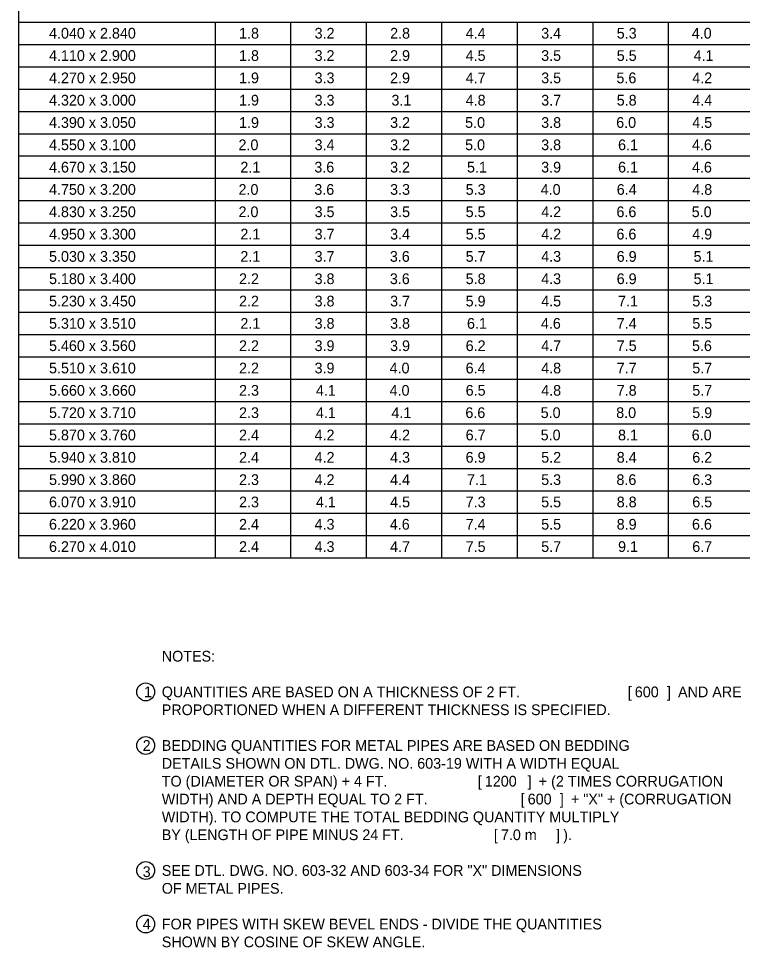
# Model space of a CAD drawing. Extents: x 49991.4 to 50047.6, y 49987.6 to 50011.4.
# Drawn here: x 50039.46 to 50043.52, y 49988.2 to 49993.4 of the extents above; entities that cross this region are included whole.
import ezdxf

# ---------------------------------------------------------------- set-up
doc = ezdxf.new("R2010")
doc.units = 0
doc.layers.add('Default', color=7, linetype='Continuous')
doc.layers.add('Level 2', color=7, linetype='Continuous')

msp = doc.modelspace()

# ---------------------------------------------------------------- linework, layer by layer
at = {"layer": 'Default'}
msp.add_circle((50040.1762, 49988.3294), 0.05, dxfattribs=at)
at = {"layer": 'Level 2'}
for p, q in [((50039.4641, 49998.1607), (50039.4641, 49990.3807)), ((50039.4641, 49993.3807), (50047.3341, 49993.3807)), ((50040.5645, 49993.3807), (50040.5645, 49990.3807)), ((50040.9876, 49993.3807), (50040.9876, 49990.3807)), ((50041.4107, 49993.3807), (50041.4107, 49990.3807)), ((50041.8338, 49993.3807), (50041.8338, 49990.3807)), ((50042.2569, 49993.3807), (50042.2569, 49990.3807)), ((50042.68, 49993.3807), (50042.68, 49990.3807)), ((50043.1031, 49993.3807), (50043.1031, 49990.3807)), ((50039.4641, 49993.2557), (50047.3341, 49993.2557)), ((50039.4641, 49993.1307), (50047.3341, 49993.1307)), ((50039.4641, 49993.0057), (50047.3341, 49993.0057)), ((50039.4641, 49992.8807), (50047.3341, 49992.8807)), ((50039.4641, 49992.7557), (50047.3341, 49992.7557)), ((50039.4641, 49992.6307), (50047.3341, 49992.6307)), ((50039.4641, 49992.5057), (50047.3341, 49992.5057)), ((50039.4641, 49992.3807), (50047.3341, 49992.3807)), ((50039.4641, 49992.2557), (50047.3341, 49992.2557)), ((50039.4641, 49992.1307), (50047.3341, 49992.1307)), ((50039.4641, 49992.0057), (50047.3341, 49992.0057)), ((50039.4641, 49991.8807), (50047.3341, 49991.8807)), ((50039.4641, 49991.7557), (50047.3341, 49991.7557)), ((50039.4641, 49991.6307), (50047.3341, 49991.6307)), ((50039.4641, 49991.5057), (50047.3341, 49991.5057)), ((50039.4641, 49991.3807), (50047.3341, 49991.3807)), ((50039.4641, 49991.2557), (50047.3341, 49991.2557)), ((50039.4641, 49991.1307), (50047.3341, 49991.1307)), ((50039.4641, 49991.0057), (50047.3341, 49991.0057)), ((50039.4641, 49990.8807), (50047.3341, 49990.8807)), ((50039.4641, 49990.7557), (50047.3341, 49990.7557)), ((50039.4641, 49990.6307), (50047.3341, 49990.6307)), ((50039.4641, 49990.5057), (50047.3341, 49990.5057)), ((50039.4641, 49990.3807), (50047.3341, 49990.3807))]:
    msp.add_line(p, q, dxfattribs=at)
for centre in [(50040.1762, 49989.6294), (50040.1762, 49989.3294), (50040.1762, 49988.6294)]:
    msp.add_circle(centre, 0.05, dxfattribs=at)

# ---------------------------------------------------------------- texts
at = {"layer": 'Default'}
msp.add_text('4', height=0.06, dxfattribs=at).set_placement((50040.1592, 49988.2994))
at = {"layer": 'Level 2'}
for s, p in [('4.040 x 2.840', (50039.6346, 49993.2882)), ('1.8', (50040.6991, 49993.2882)), ('3.2', (50041.1222, 49993.2882)), ('2.8', (50041.5453, 49993.2882)), ('4.4', (50041.9684, 49993.2882)), ('3.4', (50042.3915, 49993.2882)), ('5.3', (50042.8146, 49993.2882)), ('4.0', (50043.2347, 49993.2882)), ('4.110 x 2.900', (50039.6346, 49993.1632)), ('1.8', (50040.6991, 49993.1632)), ('3.2', (50041.1222, 49993.1632)), ('2.9', (50041.5451, 49993.1632)), ('4.5', (50041.9684, 49993.1632)), ('3.5', (50042.3915, 49993.1632)), ('5.5', (50042.8146, 49993.1632)), ('4.1', (50043.2451, 49993.1632)), ('4.270 x 2.950', (50039.6346, 49993.0382)), ('1.9', (50040.6989, 49993.0382)), ('3.3', (50041.1222, 49993.0382)), ('2.9', (50041.5451, 49993.0382)), ('4.7', (50041.9684, 49993.0382)), ('3.5', (50042.3915, 49993.0382)), ('5.6', (50042.813, 49993.0382)), ('4.2', (50043.2377, 49993.0382)), ('4.320 x 3.000', (50039.6346, 49992.9132)), ('1.9', (50040.6989, 49992.9132)), ('3.3', (50041.1222, 49992.9132)), ('3.1', (50041.5527, 49992.9132)), ('4.8', (50041.9684, 49992.9132)), ('3.7', (50042.3915, 49992.9132)), ('5.8', (50042.8146, 49992.9132)), ('4.4', (50043.2377, 49992.9132)), ('4.390 x 3.050', (50039.6346, 49992.7882)), ('1.9', (50040.6989, 49992.7882)), ('3.3', (50041.1222, 49992.7882)), ('3.2', (50041.5453, 49992.7882)), ('5.0', (50041.9654, 49992.7882)), ('3.8', (50042.3915, 49992.7882)), ('6.0', (50042.8116, 49992.7882)), ('4.5', (50043.2377, 49992.7882)), ('4.550 x 3.100', (50039.6346, 49992.6632)), ('2.0', (50040.6961, 49992.6632)), ('3.4', (50041.1222, 49992.6632)), ('3.2', (50041.5453, 49992.6632)), ('5.0', (50041.9654, 49992.6632)), ('3.8', (50042.3915, 49992.6632)), ('6.1', (50042.822, 49992.6632)), ('4.6', (50043.2361, 49992.6632)), ('4.670 x 3.150', (50039.6346, 49992.5382)), ('2.1', (50040.7065, 49992.5382)), ('3.6', (50041.1206, 49992.5382)), ('3.2', (50041.5453, 49992.5382)), ('5.1', (50041.9758, 49992.5382)), ('3.9', (50042.3913, 49992.5382)), ('6.1', (50042.822, 49992.5382)), ('4.6', (50043.2361, 49992.5382)), ('4.750 x 3.200', (50039.6346, 49992.4132)), ('2.0', (50040.6961, 49992.4132)), ('3.6', (50041.1206, 49992.4132)), ('3.3', (50041.5453, 49992.4132)), ('5.3', (50041.9684, 49992.4132)), ('4.0', (50042.3885, 49992.4132)), ('6.4', (50042.8146, 49992.4132)), ('4.8', (50043.2377, 49992.4132)), ('4.830 x 3.250', (50039.6346, 49992.2882)), ('2.0', (50040.6961, 49992.2882)), ('3.5', (50041.1222, 49992.2882)), ('3.5', (50041.5453, 49992.2882)), ('5.5', (50041.9684, 49992.2882)), ('4.2', (50042.3915, 49992.2882)), ('6.6', (50042.813, 49992.2882)), ('5.0', (50043.2347, 49992.2882)), ('4.950 x 3.300', (50039.6346, 49992.1632)), ('2.1', (50040.7065, 49992.1632)), ('3.7', (50041.1222, 49992.1632)), ('3.4', (50041.5453, 49992.1632)), ('5.5', (50041.9684, 49992.1632)), ('4.2', (50042.3915, 49992.1632)), ('6.6', (50042.813, 49992.1632)), ('4.9', (50043.2375, 49992.1632)), ('5.030 x 3.350', (50039.6346, 49992.0382)), ('2.1', (50040.7065, 49992.0382)), ('3.7', (50041.1222, 49992.0382)), ('3.6', (50041.5437, 49992.0382)), ('5.7', (50041.9684, 49992.0382)), ('4.3', (50042.3915, 49992.0382)), ('6.9', (50042.8144, 49992.0382)), ('5.1', (50043.2451, 49992.0382)), ('5.180 x 3.400', (50039.6346, 49991.9132)), ('2.2', (50040.6991, 49991.9132)), ('3.8', (50041.1222, 49991.9132)), ('3.6', (50041.5437, 49991.9132)), ('5.8', (50041.9684, 49991.9132)), ('4.3', (50042.3915, 49991.9132)), ('6.9', (50042.8144, 49991.9132)), ('5.1', (50043.2451, 49991.9132)), ('5.230 x 3.450', (50039.6346, 49991.7882)), ('2.2', (50040.6991, 49991.7882)), ('3.8', (50041.1222, 49991.7882)), ('3.7', (50041.5453, 49991.7882)), ('5.9', (50041.9682, 49991.7882)), ('4.5', (50042.3915, 49991.7882)), ('7.1', (50042.822, 49991.7882)), ('5.3', (50043.2377, 49991.7882)), ('5.310 x 3.510', (50039.6346, 49991.6632)), ('2.1', (50040.7065, 49991.6632)), ('3.8', (50041.1222, 49991.6632)), ('3.8', (50041.5453, 49991.6632)), ('6.1', (50041.9758, 49991.6632)), ('4.6', (50042.3899, 49991.6632)), ('7.4', (50042.8146, 49991.6632)), ('5.5', (50043.2377, 49991.6632)), ('5.460 x 3.560', (50039.6346, 49991.5382)), ('2.2', (50040.6991, 49991.5382)), ('3.9', (50041.122, 49991.5382)), ('3.9', (50041.5451, 49991.5382)), ('6.2', (50041.9684, 49991.5382)), ('4.7', (50042.3915, 49991.5382)), ('7.5', (50042.8146, 49991.5382)), ('5.6', (50043.2361, 49991.5382)), ('5.510 x 3.610', (50039.6346, 49991.4132)), ('2.2', (50040.6991, 49991.4132)), ('3.9', (50041.122, 49991.4132)), ('4.0', (50041.5423, 49991.4132)), ('6.4', (50041.9684, 49991.4132)), ('4.8', (50042.3915, 49991.4132)), ('7.7', (50042.8146, 49991.4132)), ('5.7', (50043.2377, 49991.4132)), ('5.660 x 3.660', (50039.6346, 49991.2882)), ('2.3', (50040.6991, 49991.2882)), ('4.1', (50041.1296, 49991.2882)), ('4.0', (50041.5423, 49991.2882)), ('6.5', (50041.9684, 49991.2882)), ('4.8', (50042.3915, 49991.2882)), ('7.8', (50042.8146, 49991.2882)), ('5.7', (50043.2377, 49991.2882)), ('5.720 x 3.710', (50039.6346, 49991.1632)), ('2.3', (50040.6991, 49991.1632)), ('4.1', (50041.1296, 49991.1632)), ('4.1', (50041.5527, 49991.1632)), ('6.6', (50041.9668, 49991.1632)), ('5.0', (50042.3885, 49991.1632)), ('8.0', (50042.8116, 49991.1632)), ('5.9', (50043.2375, 49991.1632)), ('5.870 x 3.760', (50039.6346, 49991.0382)), ('2.4', (50040.6991, 49991.0382)), ('4.2', (50041.1222, 49991.0382)), ('4.2', (50041.5453, 49991.0382)), ('6.7', (50041.9684, 49991.0382)), ('5.0', (50042.3885, 49991.0382)), ('8.1', (50042.822, 49991.0382)), ('6.0', (50043.2347, 49991.0382)), ('5.940 x 3.810', (50039.6346, 49990.9132)), ('2.4', (50040.6991, 49990.9132)), ('4.2', (50041.1222, 49990.9132)), ('4.3', (50041.5453, 49990.9132)), ('6.9', (50041.9682, 49990.9132)), ('5.2', (50042.3915, 49990.9132)), ('8.4', (50042.8146, 49990.9132)), ('6.2', (50043.2377, 49990.9132)), ('5.990 x 3.860', (50039.6346, 49990.7882)), ('2.3', (50040.6991, 49990.7882)), ('4.2', (50041.1222, 49990.7882)), ('4.4', (50041.5453, 49990.7882)), ('7.1', (50041.9758, 49990.7882)), ('5.3', (50042.3915, 49990.7882)), ('8.6', (50042.813, 49990.7882)), ('6.3', (50043.2377, 49990.7882)), ('6.070 x 3.910', (50039.6346, 49990.6632)), ('2.3', (50040.6991, 49990.6632)), ('4.1', (50041.1296, 49990.6632)), ('4.5', (50041.5453, 49990.6632)), ('7.3', (50041.9684, 49990.6632)), ('5.5', (50042.3915, 49990.6632)), ('8.8', (50042.8146, 49990.6632)), ('6.5', (50043.2377, 49990.6632)), ('6.220 x 3.960', (50039.6346, 49990.5382)), ('2.4', (50040.6991, 49990.5382)), ('4.3', (50041.1222, 49990.5382)), ('4.6', (50041.5437, 49990.5382)), ('7.4', (50041.9684, 49990.5382)), ('5.5', (50042.3915, 49990.5382)), ('8.9', (50042.8144, 49990.5382)), ('6.6', (50043.2361, 49990.5382)), ('6.270 x 4.010', (50039.6346, 49990.4132)), ('2.4', (50040.6991, 49990.4132)), ('4.3', (50041.1222, 49990.4132)), ('4.7', (50041.5453, 49990.4132)), ('7.5', (50041.9684, 49990.4132)), ('5.7', (50042.3915, 49990.4132)), ('9.1', (50042.822, 49990.4132)), ('6.7', (50043.2377, 49990.4132)), ('NOTES:', (50040.2662, 49989.7994)), ('1', (50040.1665, 49989.5994)), ('QUANTITIES ARE BASED ON A THICKNESS OF 2 FT. ', (50040.2662, 49989.5994)), ('[', (50042.8762, 49989.5994)), ('600', (50042.9159, 49989.5994)), (']', (50043.0959, 49989.5994)), (' AND ARE', (50043.1356, 49989.5994)), ('PROPORTIONED WHEN A DIFFERENT THICKNESS IS SPECIFIED.', (50040.2662, 49989.4994)), ('2', (50040.1592, 49989.2994)), ('BEDDING QUANTITIES FOR METAL PIPES ARE BASED ON BEDDING', (50040.2662, 49989.2994)), ('DETAILS SHOWN ON DTL. DWG. NO. 603-19 WITH A WIDTH EQUAL ', (50040.2662, 49989.1994)), ('TO (DIAMETER OR SPAN) + 4 FT. ', (50040.2662, 49989.0994)), ('[', (50042.0362, 49989.0994)), ('1200', (50042.0759, 49989.0994)), (']', (50042.3159, 49989.0994)), (' + (2 TIMES CORRUGATION ', (50042.3556, 49989.0994)), ('WIDTH) AND A DEPTH EQUAL TO 2 FT. ', (50040.2662, 49988.9994)), ('[', (50042.2762, 49988.9994)), ('600', (50042.3159, 49988.9994)), (']', (50042.4959, 49988.9994)), (' + "X" + (CORRUGATION ', (50042.5356, 49988.9994)), ('WIDTH). TO COMPUTE THE TOTAL BEDDING QUANTITY MULTIPLY ', (50040.2662, 49988.8994)), ('BY (LENGTH OF PIPE MINUS 24 FT. ', (50040.2662, 49988.7994)), ('[', (50042.1262, 49988.7994)), ('7.0 m', (50042.1659, 49988.7994)), (']', (50042.4749, 49988.7994)), (').', (50042.5146, 49988.7994)), ('3', (50040.1592, 49988.5926)), ('SEE DTL. DWG. NO. 603-32 AND 603-34 FOR "X" DIMENSIONS', (50040.2662, 49988.5994)), ('OF METAL PIPES.', (50040.2662, 49988.4994)), ('FOR PIPES WITH SKEW BEVEL ENDS - DIVIDE THE QUANTITIES', (50040.2662, 49988.2994)), ('SHOWN BY COSINE OF SKEW ANGLE.', (50040.2662, 49988.1994))]:
    msp.add_text(s, height=0.06, dxfattribs=at).set_placement(p)

doc.saveas('drawing.dxf')
